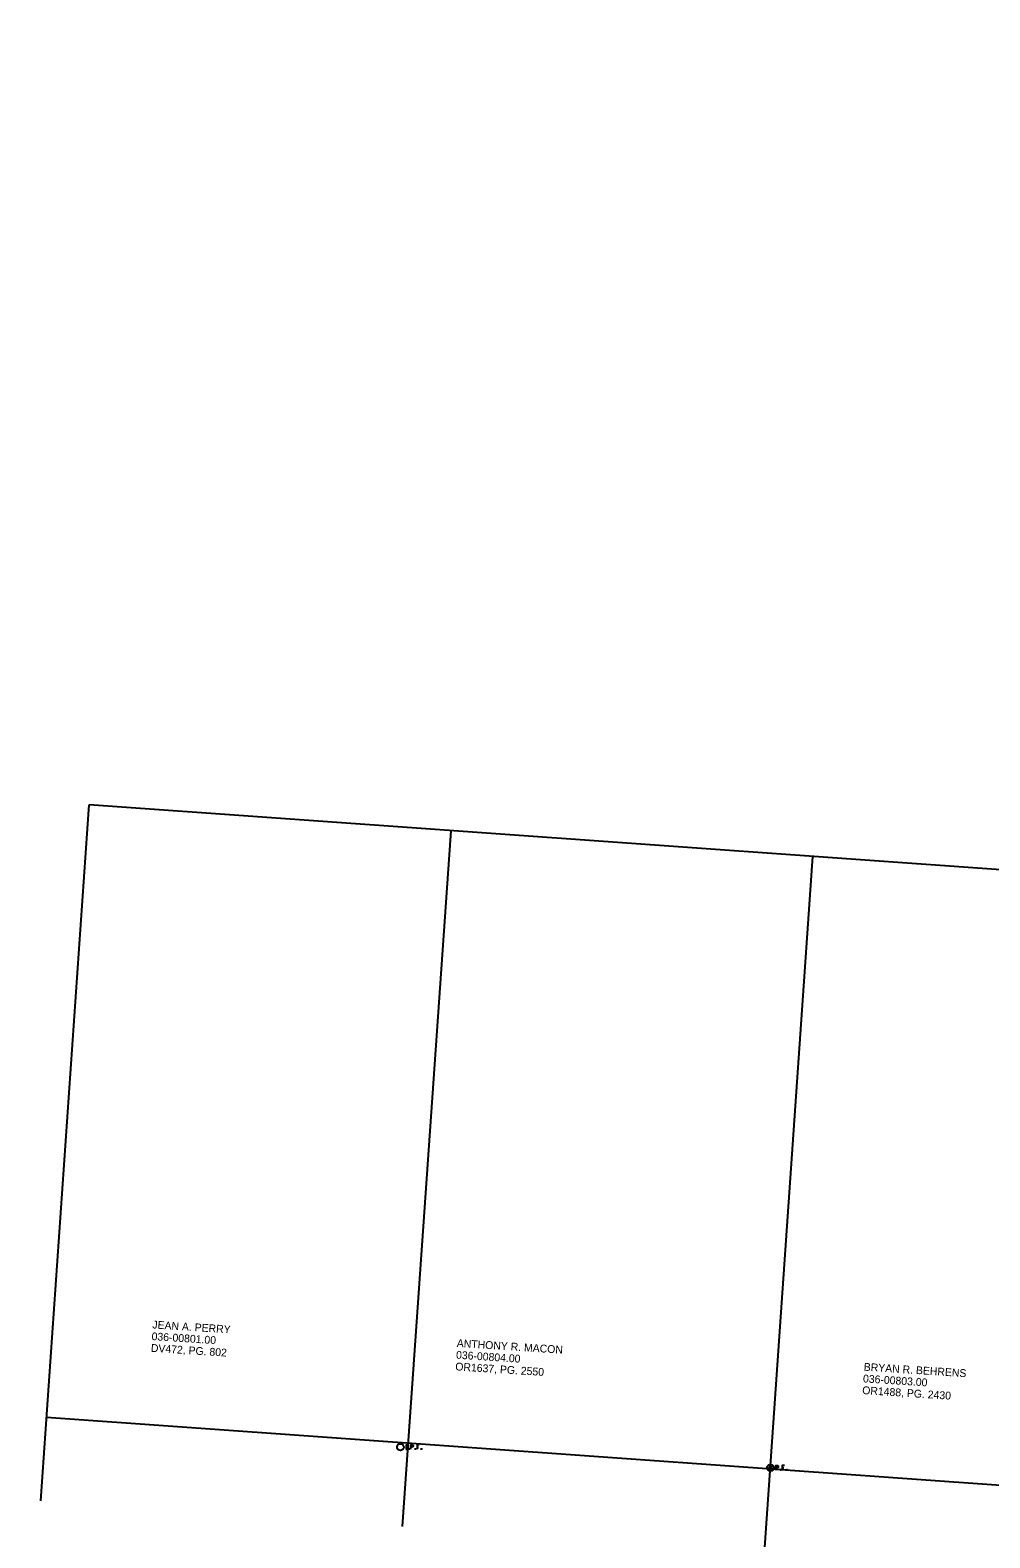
# Model space of a CAD drawing. Extents: x 1898254 to 1901377, y 701554 to 704886.
# Drawn here: x 1898624 to 1898968, y 703301 to 703841 of the extents above; entities that cross this region are included whole.
import ezdxf

# ---------------------------------------------------------------- set-up
doc = ezdxf.new("R2010")
doc.units = 0
for name, color, linetype in [('DV_X_Property_Line', 7, 'Continuous'), ('DV_X_Text', 7, 'Continuous'), ('RW_X_Fee_RW', 7, 'Continuous'), ('SC_Scratch2', 7, 'Continuous'), ('SV_X_Mon_Cells_Found', 7, 'Continuous')]:
    doc.layers.add(name, color=color, linetype=linetype)

msp = doc.modelspace()

# ---------------------------------------------------------------- linework, layer by layer
at = {"layer": 'DV_X_Property_Line'}
for p, q in [((1898628.06, 703314.3), (1898645.43, 703563.69)), ((1898994.39, 703538.88), (1898645.43, 703563.69)), ((1898757.73, 703305.08), (1898775.1, 703554.47)), ((1898887.4, 703295.86), (1898904.77, 703545.25))]:
    msp.add_line(p, q, dxfattribs=at)
at = {"layer": 'RW_X_Fee_RW'}
msp.add_line((1898630.14, 703344.22), (1899526.13, 703280.51), dxfattribs=at)
at = {"layer": 'SC_Scratch2'}
msp.add_circle((1899815.76, 703229.84), 1561.35, dxfattribs=at)
at = {"layer": 'SV_X_Mon_Cells_Found'}
for points in [[(1898758.93, 703334.36), (1898759.28, 703334.36)], [(1898758.93, 703332.76), (1898759.28, 703332.76)], [(1898759.11, 703332.76), (1898759.11, 703334.36)], [(1898760.07, 703332.97), (1898760.12, 703332.97), (1898760.16, 703332.95), (1898760.19, 703332.9), (1898760.19, 703332.83), (1898760.16, 703332.78), (1898760.12, 703332.76), (1898760.07, 703332.76), (1898760.03, 703332.78), (1898760, 703332.83), (1898760, 703332.9), (1898760.03, 703332.95), (1898760.07, 703332.97)], [(1898760.67, 703332.76), (1898760.67, 703334.36), (1898761.2, 703334.36), (1898761.26, 703334.34), (1898761.33, 703334.32), (1898761.37, 703334.29), (1898761.4, 703334.27), (1898761.45, 703334.21), (1898761.48, 703334.14), (1898761.5, 703334.04), (1898761.5, 703333.89), (1898761.49, 703333.84), (1898761.47, 703333.76), (1898761.42, 703333.68), (1898761.38, 703333.64), (1898761.35, 703333.61), (1898761.29, 703333.59), (1898761.2, 703333.58), (1898760.67, 703333.58)], [(1898762.32, 703332.97), (1898762.37, 703332.97), (1898762.4, 703332.95), (1898762.44, 703332.9), (1898762.44, 703332.83), (1898762.4, 703332.78), (1898762.37, 703332.76), (1898762.32, 703332.76), (1898762.28, 703332.78), (1898762.25, 703332.83), (1898762.25, 703332.9), (1898762.28, 703332.95), (1898762.32, 703332.97)], [(1898763.68, 703334.36), (1898762.92, 703334.36), (1898762.92, 703332.76)], [(1898762.92, 703333.58), (1898763.46, 703333.58)], [(1898764.47, 703332.97), (1898764.52, 703332.97), (1898764.55, 703332.95), (1898764.59, 703332.9), (1898764.59, 703332.83), (1898764.55, 703332.78), (1898764.52, 703332.76), (1898764.47, 703332.76), (1898764.43, 703332.78), (1898764.4, 703332.83), (1898764.4, 703332.9), (1898764.43, 703332.95), (1898764.47, 703332.97)], [(1898891.51, 703325.34), (1898891.51, 703326.94), (1898892.04, 703326.94), (1898892.09, 703326.93), (1898892.17, 703326.91), (1898892.2, 703326.88), (1898892.24, 703326.86), (1898892.28, 703326.79), (1898892.31, 703326.73), (1898892.34, 703326.63), (1898892.34, 703326.48), (1898892.32, 703326.43), (1898892.3, 703326.35), (1898892.26, 703326.26), (1898892.21, 703326.23), (1898892.18, 703326.2), (1898892.13, 703326.18), (1898892.04, 703326.16), (1898891.51, 703326.16)], [(1898894.52, 703326.94), (1898893.76, 703326.94), (1898893.76, 703325.34)], [(1898893.15, 703325.56), (1898893.21, 703325.56), (1898893.24, 703325.53), (1898893.27, 703325.48), (1898893.27, 703325.42), (1898893.24, 703325.37), (1898893.21, 703325.34), (1898893.15, 703325.34), (1898893.12, 703325.37), (1898893.09, 703325.42), (1898893.09, 703325.48), (1898893.12, 703325.53), (1898893.15, 703325.56)], [(1898893.76, 703326.16), (1898894.3, 703326.16)], [(1898895.3, 703325.56), (1898895.36, 703325.56), (1898895.39, 703325.53), (1898895.42, 703325.48), (1898895.42, 703325.42), (1898895.39, 703325.37), (1898895.36, 703325.34), (1898895.3, 703325.34), (1898895.27, 703325.37), (1898895.23, 703325.42), (1898895.23, 703325.48), (1898895.27, 703325.53), (1898895.3, 703325.56)]]:
    msp.add_lwpolyline(points, dxfattribs=at)
for centre, radius in [((1898756.92, 703333.56), 1.2), ((1898889.51, 703326.14), 1.2), ((1898889.51, 703326.14), 0.495)]:
    msp.add_circle(centre, radius, dxfattribs=at)

# ---------------------------------------------------------------- texts
at = {"layer": 'DV_X_Text'}
for s, p in [('JEAN A. PERRY', (1898667.99, 703376.1)), ('DV472, PG. 802', (1898667.46, 703367.72)), ('036-00801.00', (1898667.72, 703371.91)), ('ANTHONY R. MACON ', (1898777.08, 703369.46)), ('036-00804.00', (1898776.81, 703365.27)), ('OR1637, PG. 2550', (1898776.54, 703361.08)), ('036-00803.00', (1898922.63, 703356.77)), ('BRYAN R. BEHRENS', (1898922.9, 703360.96)), ('OR1488, PG. 2430', (1898922.36, 703352.58))]:
    msp.add_text(s, height=2.8, rotation=356.3351, dxfattribs=at).set_placement(p)

doc.saveas('drawing.dxf')
